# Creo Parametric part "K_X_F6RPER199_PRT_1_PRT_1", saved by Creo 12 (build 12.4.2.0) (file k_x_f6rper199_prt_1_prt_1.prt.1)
Units: Custom; MM, KILOGRAM, SECS

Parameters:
  PTC_WM_ITERATION = "0"
  PTC_WM_VERSION = "-.0"
  PTC_WM_LIFECYCLE_STATE = "In Work"
  PTC_WM_LIFECYCLE = "MO_CADDocument"
  PTC_WM_CREATED_BY = "Maximilian Roepper (Z0017RMS: MO)"
  PTC_WM_CREATED_ON = "18-Sep-26 11:36:42 AM"
  PTC_WM_MODIFIED_BY = "Maximilian Roepper (Z0017RMS: MO)"
  PTC_WM_MODIFIED_ON = "18-Sep-26 11:36:46 AM"
  PDMLINKNUMBER = "PDM000071454997"
  PTC_WM_NAME = "k_x_f6rper199_prt_1_prt_1.prt"
  PTC_WM_NUMBER = "PDM000071454997"

Other parameters: WEIGHT, WEIGHT_FACTOR, WEIGHT_ADD, _MASS_TEMP, _DIFF_TEMP, MC_ERRORS, SUPPLIER

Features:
  1. coordinate system
  2. datum plane "PRT_YZ"
  3. datum plane "PRT_XY"
  4. datum plane "PRT_XZ"
  5. coordinate system
  6. datum axis
  7. datum axis
  8. datum axis
  9. coordinate system
  10. imported feature
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
Other named items: PRT, SIEMENS_MO, DRW_VIEW_ORG, PRT_X, PRT_Y, PRT_Z, CS0, ROUGH_GROB

Layers: 00_STD_CSYS-KSYS, 01_STD_PLANES-EBENEN, 02_STD_AXES-ACHSEN, 03_STD_CSYS-KSYS, 24_IMPORT_FEAT-IMPORT_KE

Surfaces: 14 plane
